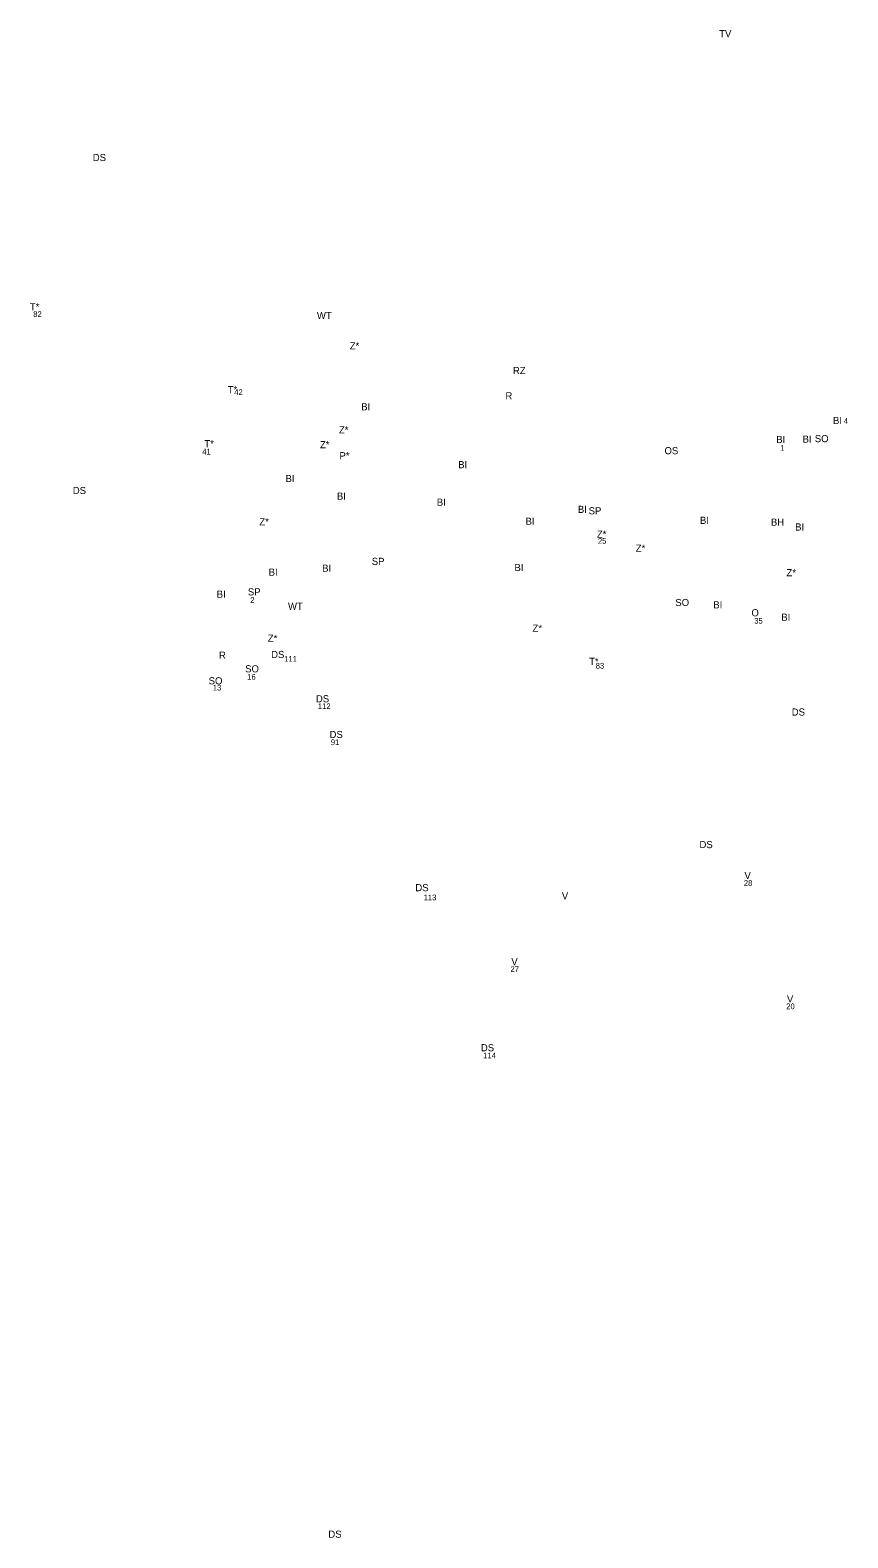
# Model space of a CAD drawing. Extents: x -521559 to -516922, y -1189648 to -1185402.
# Drawn here: x -520400 to -519252, y -1188671 to -1186556 of the extents above; entities that cross this region are included whole.
import ezdxf

# ---------------------------------------------------------------- set-up
doc = ezdxf.new("R2010")
doc.units = 0
for name, color, linetype in [('bydleni_n', 7, 'Continuous'), ('bydleni_s', 7, 'Continuous'), ('fpl_id', 7, 'Continuous'), ('rekreace_s', 7, 'Continuous'), ('s_zelen_n', 7, 'Continuous'), ('s_zelen_s', 7, 'Continuous'), ('sm_vyuziti_n', 7, 'Continuous'), ('sm_vyuziti_s', 7, 'Continuous'), ('v_infrastr_n', 7, 'Continuous'), ('v_infrastr_s', 7, 'Continuous'), ('voda_s', 7, 'Continuous'), ('vyroba_n', 7, 'Continuous'), ('vyroba_s', 7, 'Continuous')]:
    doc.layers.add(name, color=color, linetype=linetype)

msp = doc.modelspace()

# ---------------------------------------------------------------- texts
at = {"layer": 'bydleni_n'}
for p in [(-519273.3, -1187108.7), (-519352.9, -1187135.3)]:
    msp.add_text('BI', height=10, dxfattribs=at).set_placement(p)
at = {"layer": 'bydleni_s'}
for s, p in [('BI', (-519935.2, -1187089.4)), ('BI', (-519316, -1187134.8)), ('BI', (-519799.1, -1187170.6)), ('BI', (-520041.4, -1187190.1)), ('BI', (-519969.3, -1187214.7)), ('BI', (-519829.1, -1187223.3)), ('BI', (-519631.2, -1187233.3)), ('BI', (-519459.9, -1187248.7)), ('BI', (-519704.7, -1187250)), ('BH', (-519360.4, -1187251.2)), ('BI', (-519326.4, -1187258)), ('BI', (-520065, -1187321.3)), ('BI', (-519990, -1187315.8)), ('BI', (-519720.2, -1187314.9)), ('BI', (-520137.9, -1187352.2)), ('BI', (-519441.2, -1187367.1)), ('BI', (-519345.8, -1187384.6))]:
    msp.add_text(s, height=10, dxfattribs=at).set_placement(p)
at = {"layer": 'fpl_id'}
for s, p in [('82', (-520395.3, -1186958.6)), ('42', (-520113.3, -1187068)), ('4', (-519258.1, -1187108.2)), ('41', (-520158.2, -1187151.4)), ('1', (-519347.4, -1187146.2)), ('25', (-519603.1, -1187276.6)), ('2', (-520090.8, -1187359.4)), ('35', (-519383.8, -1187388.6)), ('111', (-520043.3, -1187442.1)), ('83', (-519606.2, -1187451.6)), ('16', (-520095.1, -1187467.2)), ('13', (-520143.4, -1187482.3)), ('112', (-519996, -1187508.4)), ('91', (-519977.8, -1187558.9)), ('113', (-519847.6, -1187776.5)), ('28', (-519398.4, -1187756.3)), ('27', (-519725.8, -1187877)), ('20', (-519338.9, -1187929.2)), ('114', (-519764, -1187998.2))]:
    msp.add_text(s, height=8, dxfattribs=at).set_placement(p)
at = {"layer": 'rekreace_s'}
for s, p in [('RZ', (-519722.3, -1187038.7)), ('R', (-519732.9, -1187074)), ('R', (-520134.7, -1187437.8))]:
    msp.add_text(s, height=10, dxfattribs=at).set_placement(p)
at = {"layer": 's_zelen_n'}
msp.add_text('Z*', height=10, dxfattribs=at).set_placement((-519604.5, -1187268.1))
at = {"layer": 's_zelen_s'}
for p in [(-519951.3, -1187004.1), (-519966.5, -1187121.9), (-519993, -1187142.6), (-520078.1, -1187250.7), (-519550, -1187287.7), (-519338.5, -1187322), (-520066.2, -1187413.9), (-519694.9, -1187399.8)]:
    msp.add_text('Z*', height=10, dxfattribs=at).set_placement(p)
at = {"layer": 'sm_vyuziti_n'}
for s, p in [('SP', (-520094.2, -1187349)), ('SO', (-520098, -1187456.9)), ('SO', (-520149.2, -1187473.7))]:
    msp.add_text(s, height=10, dxfattribs=at).set_placement(p)
at = {"layer": 'sm_vyuziti_s'}
for s, p in [('SO', (-519298.8, -1187134.1)), ('SP', (-519616.1, -1187235.3)), ('SP', (-519920.4, -1187306.2)), ('SO', (-519494.5, -1187363.9))]:
    msp.add_text(s, height=10, dxfattribs=at).set_placement(p)
at = {"layer": 'v_infrastr_n'}
for s, p in [('T*', (-520400, -1186949.2)), ('T*', (-520122.4, -1187065.4)), ('T*', (-520155.3, -1187141.2)), ('O', (-519387.7, -1187378.3)), ('DS', (-520061.6, -1187436.8)), ('T*', (-519615.4, -1187446.4)), ('DS', (-519998.7, -1187498.9)), ('DS', (-519979.6, -1187549)), ('DS', (-519859.2, -1187763.8)), ('DS', (-519767.3, -1187988.2))]:
    msp.add_text(s, height=10, dxfattribs=at).set_placement(p)
at = {"layer": 'v_infrastr_s'}
for s, p in [('TV', (-519433, -1186566.3)), ('DS', (-520311.8, -1186739.9)), ('P*', (-519965.7, -1187158.1)), ('OS', (-519509.7, -1187151)), ('DS', (-520339.8, -1187206.8)), ('DS', (-519331.2, -1187517.5)), ('DS', (-519460.6, -1187703.4)), ('DS', (-519981.3, -1188670.4))]:
    msp.add_text(s, height=10, dxfattribs=at).set_placement(p)
at = {"layer": 'voda_s'}
for p in [(-519997.3, -1186961.5), (-520037.9, -1187369.2)]:
    msp.add_text('WT', height=10, dxfattribs=at).set_placement(p)
at = {"layer": 'vyroba_n'}
for p in [(-519397.5, -1187746.8), (-519724.6, -1187867.5), (-519337.9, -1187919.7)]:
    msp.add_text('V', height=10, dxfattribs=at).set_placement(p)
at = {"layer": 'vyroba_s'}
msp.add_text('V', height=10, dxfattribs=at).set_placement((-519653.7, -1187775.2))

doc.saveas('drawing.dxf')
